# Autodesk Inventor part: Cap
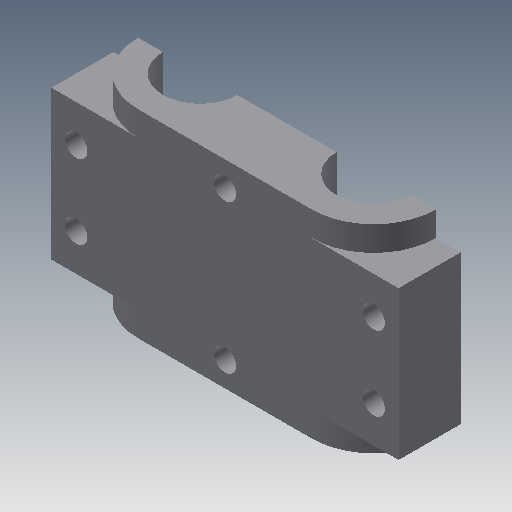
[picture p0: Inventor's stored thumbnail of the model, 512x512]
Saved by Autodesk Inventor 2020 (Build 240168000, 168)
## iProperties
Created: 2002-02
Part Number: Cap
Document SubType Name: Modeling
Designer: ***
Density: 1 g/cm^3
Material: Generic
Appearance: Default
Control State: 0
Master: False
Checked Out: False
Shininess: 77.0
Length Units: 11269
Angle Units: 11279
Time Units: 11290
Mass Units: 11283
Length Display Precision: 3
Angle Display Precision: 2
Density: 0.0
Volumn: 0.0
Area: 0.0
PropertySet Name: Model Information
Author: ***
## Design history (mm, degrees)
sketch "Sketch2"
  geometry: L1 (-17.5, 12.5)-(17.5, 12.5); L2 (30, 0)-(25, 0); L3 (10, 0)-(-10, 0); L4 (-25, 0)-(-30, 0); A1 r 12.5 centre (-17.5, 0) between (-17.5, 12.5) and (-30, 0); A2 r 12.5 centre (17.5, 0) between (30, 0) and (17.5, 12.5); A3 r 7.5 centre (17.5, 0) between (25, 0) and (10, 0); A4 r 7.5 centre (-17.5, 0) between (-10, 0) and (-25, 0)
  constraints: 8 end point, 8 point on circle, 4 centre point, 3 horizontal, 3 parallel, 2 coincident, 2 equal radius, 2 tangent
  dimensions: "d0" = 12.5 radius of A1; "d1" = 7.5 radius of A4; "d2" = 35 distance of A1.centre A2.centre; "d3" = 12.5 distance between parallel lines of L1 L3
extrude "Extrusion1" new body sketch "Sketch2" stored distance "d4" = 40; taper "d5" = 0 deg
workplane "Work Plane1"
sketch "Sketch3"
  geometry: L1 (-15, 12.5)-(15, 12.5); L2 (15, 12.5)-(15, 0); L3 (15, 0)-(-15, 0); L4 (-15, 0)-(-15, 12.5); L5 (-20, 0)-(20, 0) reference; L6 (-20, 12.5)-(20, 12.5) reference; L7 (20, 12.5)-(20, 0) reference
  constraints: 8 end point, 2 collinear, 2 parallel, 1 horizontal, 1 perpendicular
  dimensions: "d7" = 30 distance of L2.end L3.end; "d8" = 5 distance between parallel lines of L7 L2
extrude "Extrusion2" join sketch "Sketch3" stored distance "d9" = 40; taper "d10" = 0 deg
mirror "Mirror1"
sketch "Sketch4"
  geometry: L1 (-17.5, -35)-(0, -35) reference; L2 (-17.5, -35)-(-17.5, -5) reference; 1 further point
  dimensions: "d12" = 7.5 distance from line of L1 point (-12.5, -27.5); "d13" = 5 distance from line of L2 point (-12.5, -27.5)
hole "Hole1" sketch "Sketch4" at (-12.5, -27.5) diameter "d14" = 4.5; stored, may be unused: countersink angle "d18" = 82 deg, drill point angle "d20" = 118 deg; dims "d15" = 6, "d16" = 4, "d17" = 2, "d19" = 8
pattern_linear "Rectangular Pattern1" dims "d23" = 60, "d26" = 15
sketch "Sketch5"
  geometry: L1 (0, -40)-(35, -40) reference; L2 (-17.5, -35)-(-17.5, -5) reference; 1 further point
  dimensions: "d27" = 5 distance from line of L1 point (17.5, -35); "d28" = 35 distance from line of L2 point (17.5, -35)
hole "Hole2" sketch "Sketch5" at (17.5, -35) diameter "d29" = 4.5; stored, may be unused: countersink angle "d33" = 82 deg, drill point angle "d35" = 118 deg; dims "d30" = 6, "d31" = 4, "d32" = 2, "d34" = 8
pattern_linear "Rectangular Pattern2" dims "d38" = 30
body "Solid1"
other parameters: "d11" = 35
